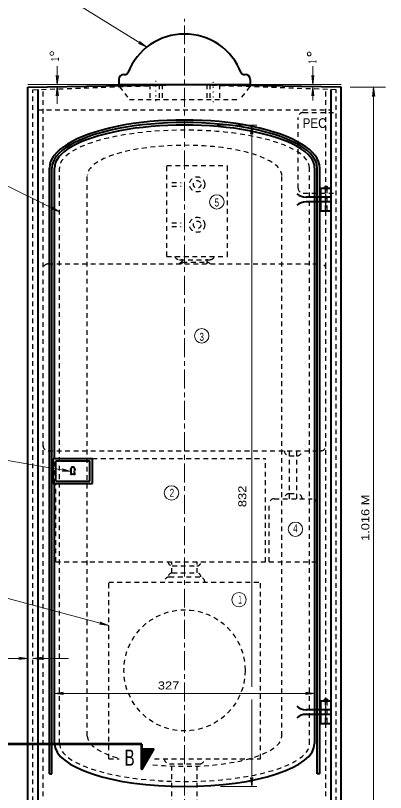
# Model space of a CAD drawing. Extents: x 312583 to 312853, y 144419 to 144586.
# Drawn here: x 312636.2 to 312671.3, y 144456.3 to 144530 of the extents above; entities that cross this region are included whole.
import ezdxf
from ezdxf.enums import TextEntityAlignment as Align

# ---------------------------------------------------------------- set-up
doc = ezdxf.new("R2010")
doc.units = 0
doc.header["$LTSCALE"] = 0.3
for name, pattern in [('DOTTED', [1.5, 0.3, -1.2]), ('LONG_DASH_SHORT_DASH', [9.9, 6, -1.2, 1.5, -1.2]), ('SHORT_DASHED', [2.7, 1.5, -1.2])]:
    doc.linetypes.add(name, pattern=pattern)
doc.layers.add('1', color=7, linetype='Continuous', lineweight=40)
doc.layers.add('2', color=7, linetype='Continuous', lineweight=13)

msp = doc.modelspace()

# ---------------------------------------------------------------- linework, layer by layer
at = {"layer": '1', "linetype": 'LONG_DASH_SHORT_DASH', "lineweight": 13}
msp.add_line((312652.2386, 144444.1359), (312652.2386, 144529.7113), dxfattribs=at)
at = {"layer": '1'}
for p, q in [((312646.0133, 144523.9613), (312646.0133, 144523.4859)), ((312646.4886, 144524.4443), (312646.6573, 144524.4443)), ((312657.8276, 144524.4443), (312657.9886, 144524.4443)), ((312658.4716, 144523.9613), (312658.4716, 144523.4859)), ((312637.3883, 144523.2253), (312652.2386, 144523.4859)), ((312637.3883, 144448.2376), (312637.3883, 144523.2253)), ((312646.0133, 144523.4859), (312658.4716, 144523.4859)), ((312646.0133, 144523.4859), (312658.4716, 144523.4859)), ((312667.0966, 144523.2253), (312652.2386, 144523.4859)), ((312667.0966, 144448.2376), (312667.0966, 144523.2253)), ((312638.3466, 144453.0293), (312638.3466, 144523.0029)), ((312666.1383, 144453.0293), (312666.1383, 144523.0029)), ((312639.4276, 144458.0586), (312639.4276, 144515.5586)), ((312639.6653, 144458.0586), (312639.6653, 144515.5586)), ((312639.9029, 144488.0046), (312639.9029, 144515.5586)), ((312664.5819, 144460.9336), (312664.5819, 144515.5586)), ((312664.8196, 144458.0586), (312664.8196, 144515.5586)), ((312665.0573, 144458.0586), (312665.0573, 144515.5586)), ((312665.1799, 144513.6419), (312666.1383, 144513.6419)), ((312665.1799, 144511.4876), (312665.1799, 144513.6419)), ((312666.1076, 144512.7833), (312663.7693, 144512.7833)), ((312666.1076, 144512.3463), (312663.7693, 144512.3463)), ((312665.1799, 144511.4876), (312666.1383, 144511.4876)), ((312639.7803, 144488.0046), (312643.4986, 144488.0046)), ((312639.7803, 144485.6126), (312639.7803, 144488.0046)), ((312643.4986, 144485.6126), (312643.4986, 144488.0046)), ((312640.0256, 144487.7669), (312643.2609, 144487.7669)), ((312640.0256, 144485.8503), (312640.0256, 144487.7669)), ((312643.2609, 144485.8503), (312643.2609, 144487.7669)), ((312639.7803, 144485.6126), (312643.4986, 144485.6126)), ((312639.9029, 144460.9336), (312639.9029, 144485.6126)), ((312640.0256, 144485.8503), (312643.2609, 144485.8503)), ((312665.1799, 144465.0046), (312666.1383, 144465.0046)), ((312665.1799, 144462.8503), (312665.1799, 144465.0046)), ((312666.1076, 144464.1459), (312663.7693, 144464.1459)), ((312666.1076, 144463.7089), (312663.7693, 144463.7089)), ((312665.1799, 144462.8503), (312666.1383, 144462.8503)), ((312639.4276, 144458.0586), (312639.6653, 144458.0586)), ((312665.0573, 144458.0586), (312664.8196, 144458.0586))]:
    msp.add_line(p, q, dxfattribs=at)
at = {"layer": '1', "linetype": 'SHORT_DASHED', "lineweight": 25}
for p, q in [((312637.8636, 144522.9876), (312652.2386, 144523.4859)), ((312646.0746, 144523.2713), (312647.0176, 144522.0446)), ((312648.9343, 144523.4859), (312648.9343, 144522.0446)), ((312649.8466, 144523.4859), (312649.8466, 144522.0446)), ((312650.1303, 144523.4859), (312650.1303, 144522.0446)), ((312666.6136, 144522.9876), (312652.2386, 144523.4859)), ((312654.3546, 144523.4859), (312654.3546, 144522.0446)), ((312654.6383, 144523.4859), (312654.6383, 144522.0446)), ((312655.5506, 144523.4859), (312655.5506, 144522.0446)), ((312658.4103, 144523.2713), (312657.4673, 144522.0446)), ((312637.8636, 144446.5586), (312637.8636, 144522.9876)), ((312638.8219, 144453.5046), (312638.8219, 144523.0183)), ((312665.6553, 144453.5046), (312665.6553, 144523.0183)), ((312666.6136, 144446.5586), (312666.6136, 144522.9876)), ((312647.0176, 144522.0446), (312657.4673, 144522.0446)), ((312638.3466, 144521.0709), (312666.1383, 144521.0709)), ((312663.0256, 144513.6419), (312663.0256, 144520.3503)), ((312663.5009, 144520.8333), (312666.6136, 144520.8333)), ((312650.5673, 144515.7963), (312656.3173, 144515.7963)), ((312650.5673, 144507.1713), (312650.5673, 144515.7963)), ((312656.3173, 144507.1713), (312656.3173, 144515.7963)), ((312640.3859, 144460.9336), (312640.3859, 144515.5586)), ((312664.0989, 144460.9336), (312664.0989, 144515.5586)), ((312643.0156, 144461.6543), (312643.0156, 144514.8379)), ((312661.4693, 144461.6543), (312661.4693, 144514.8379)), ((312651.0349, 144514.1863), (312651.9166, 144514.1863)), ((312651.0349, 144513.8259), (312651.9166, 144513.8259)), ((312665.5709, 144513.6343), (312665.5709, 144511.4799)), ((312665.7473, 144513.6343), (312665.7473, 144511.4799)), ((312663.5009, 144513.1666), (312666.6136, 144513.1666)), ((312651.0349, 144510.3529), (312651.9166, 144510.3529)), ((312651.0349, 144509.9926), (312651.9166, 144509.9926)), ((312650.5673, 144507.1713), (312656.3173, 144507.1713)), ((312652.0009, 144506.4583), (312652.0009, 144507.1713)), ((312654.4006, 144506.4583), (312654.4006, 144507.1713)), ((312639.3049, 144506.4583), (312665.1799, 144506.4583)), ((312651.7633, 144506.8569), (312654.6383, 144506.8569)), ((312652.0393, 144506.6193), (312654.3623, 144506.6193)), ((312639.3049, 144488.7253), (312665.1799, 144488.7253)), ((312662.1823, 144484.1713), (312662.1823, 144488.7253)), ((312662.9029, 144484.1713), (312662.9029, 144488.7253)), ((312639.9029, 144485.6126), (312639.9029, 144488.0046)), ((312643.4986, 144488.0046), (312659.9053, 144488.0046)), ((312662.1823, 144488.2499), (312662.9029, 144488.2499)), ((312640.0256, 144478.1836), (312640.0256, 144485.6126)), ((312660.7486, 144484.1713), (312664.3443, 144484.1713)), ((312662.1823, 144484.6543), (312662.9029, 144484.6543)), ((312660.2656, 144478.1836), (312660.2656, 144483.6959)), ((312651.0426, 144477.1333), (312651.0426, 144478.1836)), ((312651.0809, 144477.7926), (312653.4039, 144477.7926)), ((312653.4423, 144477.1333), (312653.4423, 144478.1836)), ((312660.2656, 144478.1836), (312664.8196, 144478.1836)), ((312650.8049, 144476.7499), (312653.6799, 144476.7499)), ((312651.0809, 144477.1333), (312653.4039, 144477.1333)), ((312645.0549, 144476.2669), (312659.4299, 144476.2669)), ((312645.0549, 144459.4999), (312645.0549, 144476.2669)), ((312659.4299, 144459.4999), (312659.4299, 144476.2669)), ((312665.5709, 144464.9969), (312665.5709, 144462.8503)), ((312665.7473, 144464.9969), (312665.7473, 144462.8503)), ((312645.0549, 144459.4999), (312646.0516, 144459.4999)), ((312649.3943, 144459.4999), (312659.4299, 144459.4999)), ((312650.8049, 144459.0169), (312653.6799, 144459.0169)), ((312651.0426, 144447.0416), (312651.0426, 144459.0169)), ((312653.4423, 144447.0416), (312653.4423, 144459.0169))]:
    msp.add_line(p, q, dxfattribs=at)
at = {"layer": '1', "linetype": 'DOTTED', "lineweight": 13}
for p, q in [((312649.5323, 144523.8386), (312649.5323, 144521.6613)), ((312654.9526, 144523.7389), (312654.9526, 144521.6613))]:
    msp.add_line(p, q, dxfattribs=at)
at = {"layer": '1', "lineweight": 53}
for p, q in [((312648.1983, 144460.8876), (312631.6076, 144460.8876)), ((312648.1983, 144460.4123), (312648.1983, 144460.8876))]:
    msp.add_line(p, q, dxfattribs=at)
at = {"layer": '1', "lineweight": 35}
for p, q in [((312648.1983, 144460.3969), (312649.0186, 144459.9216)), ((312648.1983, 144460.3663), (312649.0109, 144459.8986)), ((312648.1983, 144460.3356), (312648.9956, 144459.8756)), ((312648.1983, 144460.3126), (312648.9879, 144459.8603)), ((312648.1983, 144460.2819), (312648.9726, 144459.8373)), ((312648.1983, 144460.2053), (312648.9419, 144459.7759)), ((312648.1983, 144460.1746), (312648.9266, 144459.7529)), ((312648.1983, 144460.1439), (312648.9113, 144459.7376)), ((312648.1983, 144460.1209), (312648.9036, 144459.7146)), ((312648.1983, 144460.0903), (312648.8883, 144459.6916)), ((312648.1983, 144460.0596), (312648.8729, 144459.6686)), ((312648.1983, 144460.0366), (312648.8653, 144459.6533)), ((312648.1983, 144459.9753), (312648.8423, 144459.6073)), ((312648.1983, 144459.9523), (312648.8269, 144459.5919)), ((312648.1983, 144459.9293), (312648.8193, 144459.5689)), ((312648.1983, 144459.8986), (312648.8039, 144459.5459)), ((312648.1983, 144459.8679), (312648.7963, 144459.5306)), ((312648.1983, 144459.8373), (312648.7809, 144459.5076)), ((312648.1983, 144459.8143), (312648.7733, 144459.4846)), ((312648.1983, 144459.7836), (312648.7579, 144459.4693)), ((312648.2059, 144460.2589), (312648.9649, 144459.8143)), ((312648.2059, 144460.2283), (312648.9496, 144459.7989)), ((312648.2059, 144460.0059), (312648.8499, 144459.6303)), ((312648.2059, 144459.7606), (312648.7503, 144459.4386)), ((312648.2213, 144460.4123), (312649.0339, 144459.9369)), ((312648.2749, 144460.4123), (312649.0416, 144459.9676)), ((312648.3133, 144460.4123), (312649.0569, 144459.9829)), ((312648.3669, 144460.4123), (312649.0646, 144460.0059)), ((312648.4129, 144460.4123), (312649.0799, 144460.0289)), ((312648.4589, 144460.4123), (312649.0953, 144460.0443)), ((312648.5049, 144460.4123), (312649.1029, 144460.0673)), ((312648.5586, 144460.4123), (312649.1183, 144460.0903)), ((312648.6046, 144460.4123), (312649.1336, 144460.1056)), ((312648.6506, 144460.4123), (312649.1413, 144460.1286)), ((312648.7043, 144460.4123), (312649.1566, 144460.1439)), ((312648.7503, 144460.4123), (312649.1643, 144460.1669)), ((312648.7963, 144460.4123), (312649.1796, 144460.1899)), ((312648.8499, 144460.4123), (312649.1873, 144460.2053)), ((312648.8959, 144460.4123), (312649.2026, 144460.2359)), ((312648.9419, 144460.4123), (312649.2103, 144460.2513)), ((312648.9879, 144460.4123), (312649.2256, 144460.2743)), ((312649.0416, 144460.4123), (312649.2333, 144460.2973)), ((312649.0799, 144460.4123), (312649.2486, 144460.3126)), ((312649.1336, 144460.4123), (312649.2563, 144460.3356)), ((312649.1796, 144460.4123), (312649.2716, 144460.3586)), ((312649.2333, 144460.4123), (312649.2869, 144460.3739)), ((312649.2793, 144460.4123), (312649.2946, 144460.3969)), ((312648.1983, 144459.7299), (312648.7349, 144459.4233)), ((312648.1983, 144459.7069), (312648.7196, 144459.4003)), ((312648.1983, 144459.6763), (312648.7119, 144459.3773)), ((312648.1983, 144459.6456), (312648.6966, 144459.3619)), ((312648.1983, 144459.6226), (312648.6889, 144459.3389)), ((312648.1983, 144459.5919), (312648.6736, 144459.3159)), ((312648.1983, 144459.5613), (312648.6659, 144459.3006)), ((312648.1983, 144459.5383), (312648.6506, 144459.2776)), ((312648.1983, 144459.5076), (312648.6429, 144459.2546)), ((312648.1983, 144459.4769), (312648.6276, 144459.2393)), ((312648.1983, 144459.4539), (312648.6199, 144459.2163)), ((312648.1983, 144459.4309), (312648.6046, 144459.1933)), ((312648.1983, 144459.4003), (312648.5969, 144459.1703)), ((312648.1983, 144459.3696), (312648.5816, 144459.1549)), ((312648.1983, 144459.3389), (312648.5663, 144459.1319)), ((312648.1983, 144459.3159), (312648.5586, 144459.1089)), ((312648.1983, 144459.2853), (312648.5433, 144459.0936)), ((312648.1983, 144459.2623), (312648.5279, 144459.0706)), ((312648.1983, 144459.2316), (312648.5203, 144459.0476)), ((312648.1983, 144459.2086), (312648.5049, 144459.0323)), ((312648.1983, 144459.1779), (312648.4973, 144459.0093)), ((312648.1983, 144459.1473), (312648.4819, 144458.9863)), ((312648.1983, 144459.1243), (312648.4743, 144458.9709)), ((312648.1983, 144459.0936), (312648.4589, 144458.9403)), ((312648.1983, 144459.0706), (312648.4513, 144458.9249)), ((312648.1983, 144459.0399), (312648.4359, 144458.9019)), ((312648.1983, 144459.0093), (312648.4283, 144458.8789)), ((312648.1983, 144458.9863), (312648.4129, 144458.8636)), ((312648.1983, 144458.9556), (312648.4053, 144458.8406)), ((312648.1983, 144458.9326), (312648.3899, 144458.8176)), ((312648.1983, 144458.9019), (312648.3746, 144458.8023)), ((312648.1983, 144458.8713), (312648.3669, 144458.7793)), ((312648.1983, 144458.8406), (312648.3516, 144458.7563)), ((312648.1983, 144458.8176), (312648.3363, 144458.7409)), ((312648.1983, 144458.7869), (312648.3286, 144458.7179)), ((312648.1983, 144458.7639), (312648.3133, 144458.6949)), ((312648.1983, 144458.7409), (312648.3056, 144458.6719)), ((312648.1983, 144458.7103), (312648.2903, 144458.6566)), ((312648.1983, 144458.6796), (312648.2826, 144458.6336)), ((312648.1983, 144458.6489), (312648.2673, 144458.6106)), ((312648.1983, 144458.6259), (312648.2596, 144458.5953)), ((312648.1983, 144458.5953), (312648.2443, 144458.5723)), ((312648.1983, 144458.5723), (312648.2366, 144458.5493)), ((312648.1983, 144458.5416), (312648.2213, 144458.5339)), ((312648.1983, 144458.5109), (312648.2136, 144458.5109))]:
    msp.add_line(p, q, dxfattribs=at)
at = {"layer": '1', "linetype": 'SHORT_DASHED', "lineweight": 25}
msp.add_lwpolyline([(312640.0256, 144478.1836), (312659.9053, 144478.1836), (312659.9053, 144488.0046)], dxfattribs=at)
at = {"layer": '1', "lineweight": 53}
msp.add_lwpolyline([(312648.1983, 144460.4123), (312649.3099, 144460.4123), (312648.1983, 144458.4956)], close=True, dxfattribs=at)
at = {"layer": '1', "linetype": 'SHORT_DASHED', "lineweight": 25}
for centre, radius in [((312653.4384, 144514.0023), 0.7188), ((312653.4384, 144514.0023), 0.3594), ((312653.4384, 144510.1689), 0.7188), ((312653.4384, 144510.1689), 0.3594), ((312652.2405, 144467.8815), 5.75)]:
    msp.add_circle(centre, radius, dxfattribs=at)
at = {"layer": '1'}
for centre, radius, start, end in [((312652.2405, 144522.5257), 5.75, 21.1002, 158.90079), ((312646.4905, 144523.9632), 0.4792, 90, 180), ((312646.6525, 144524.6819), 0.2396, 270, 338.8998), ((312657.8285, 144524.6819), 0.2396, 201.1002, 270), ((312657.9905, 144523.9632), 0.4792, 0, 90), ((312665.6585, 144513.5971), 0.1954, 17.35766, 165.56497), ((312665.6568, 144513.6088), 0.1465, 17.35766, 165.56497), ((312665.6569, 144513.6205), 0.0977, 17.35766, 165.56497), ((312665.6528, 144513.638), 0.0244, 17.35766, 165.56497), ((312663.8309, 144514.3033), 1.5233, 231.73709, 267.53516), ((312663.8309, 144510.8244), 1.5233, 92.46484, 128.26291), ((312641.6413, 144486.9926), 0.184, 0.60951, 179.40319), ((312640.5502, 144486.7229), 0.9469, 343.7422, 16.66705), ((312641.6394, 144486.0304), 0.4638, 67.14337, 112.85662), ((312642.7286, 144486.7229), 0.9469, 163.33295, 196.2578), ((312665.6585, 144464.9616), 0.1954, 17.35766, 165.56497), ((312665.6568, 144464.9733), 0.1465, 17.35766, 165.56497), ((312665.6569, 144464.985), 0.0977, 17.35766, 165.56497), ((312665.6528, 144465.0026), 0.0244, 17.35766, 165.56497), ((312663.8309, 144465.6678), 1.5233, 231.73709, 267.53516), ((312663.8309, 144462.1889), 1.5233, 92.46484, 128.26291)]:
    msp.add_arc(centre, radius, start, end, dxfattribs=at)
at = {"layer": '1', "linetype": 'SHORT_DASHED', "lineweight": 25}
for centre, radius, start, end in [((312663.5009, 144520.3503), 0.4792, 90, 180), ((312663.5009, 144513.6419), 0.4792, 180, 270), ((312651.7613, 144507.3361), 0.4792, 199.98311, 270), ((312654.6363, 144507.3361), 0.4792, 270, 340.11484), ((312639.303, 144505.9753), 0.4792, 90, 180), ((312652.0356, 144506.229), 0.3881, 90.0198, 144.53298), ((312654.3643, 144506.229), 0.3881, 35.49, 90.0198), ((312665.178, 144505.9753), 0.4792, 0, 90), ((312639.303, 144489.2044), 0.4792, 180, 270), ((312662.1842, 144488.7272), 0.4792, 180, 270), ((312662.9029, 144488.7272), 0.4792, 270, 0), ((312665.178, 144489.2044), 0.4792, 270, 0), ((312660.7467, 144483.694), 0.4792, 90, 180), ((312662.1842, 144484.1732), 0.4792, 90, 180), ((312662.9029, 144484.1732), 0.4792, 0, 90), ((312664.3423, 144483.694), 0.4792, 0, 90), ((312651.0772, 144478.1828), 0.3881, 180, 270), ((312653.406, 144478.1828), 0.3881, 270, 0), ((312650.803, 144476.2669), 0.4792, 90, 180), ((312651.0772, 144476.7469), 0.3881, 90, 180), ((312653.406, 144476.7469), 0.3881, 0, 90), ((312653.678, 144476.2669), 0.4792, 0, 90), ((312650.803, 144459.4961), 0.4792, 180, 270), ((312653.678, 144459.4961), 0.4792, 270, 0)]:
    msp.add_arc(centre, radius, start, end, dxfattribs=at)
at = {"layer": '1'}
for centre, major_axis, ratio, start_param, end_param in [((312652.2415, 144515.5586), (12.8177, 0), 0.35514, 6.2831853, 9.424778), ((312652.2415, 144515.5586), (12.5781, 0), 0.342857, 6.2831853, 9.424778), ((312652.2415, 144515.5586), (12.3385, 0), 0.330097, 6.2831853, 9.424778), ((312652.2415, 144460.9336), (12.3385, 0), 0.330097, 3.1415927, 6.2831853)]:
    msp.add_ellipse(centre, major_axis=major_axis, ratio=ratio, start_param=start_param, end_param=end_param, dxfattribs=at)
at = {"layer": '1', "linetype": 'SHORT_DASHED', "lineweight": 25}
for centre, major_axis, ratio, start_param, end_param in [((312652.2415, 144515.5586), (11.8594, 0), 0.30303, 6.2831853, 9.424778), ((312652.2415, 144514.8398), (-9.224, 0), 0.311688, 3.1415927, 6.2831853), ((312652.2415, 144461.6523), (-9.224, 0), 0.311688, 6.2831853, 7.1291245), ((312652.2415, 144461.6523), (-9.224, 0), 0.311688, 1.2393571, 3.1415927), ((312652.2415, 144460.9336), (11.8594, 0), 0.30303, 3.1415927, 6.2831853)]:
    msp.add_ellipse(centre, major_axis=major_axis, ratio=ratio, start_param=start_param, end_param=end_param, dxfattribs=at)
at = {"layer": '2'}
for p, q in [((312647.8686, 144527.3883), (312648.1523, 144527.3346)), ((312648.6583, 144527.0203), (312647.8686, 144527.3883)), ((312647.9759, 144527.5723), (312648.1523, 144527.3346)), ((312648.6583, 144527.0203), (312647.9759, 144527.5723)), ((312640.1713, 144523.4859), (312640.1713, 144525.2339)), ((312664.4056, 144523.4859), (312664.4056, 144525.2339)), ((312640.0639, 144524.3523), (312640.1713, 144524.0763)), ((312640.1713, 144523.4859), (312640.0639, 144524.3523)), ((312640.2786, 144524.3523), (312640.1713, 144524.0763)), ((312640.1713, 144523.4859), (312640.2786, 144524.3523)), ((312664.2983, 144524.3523), (312664.4056, 144524.0763)), ((312664.4056, 144523.4859), (312664.2983, 144524.3523)), ((312664.5129, 144524.3523), (312664.4056, 144524.0763)), ((312664.4056, 144523.4859), (312664.5129, 144524.3523)), ((312652.2386, 144523.4859), (312637.3883, 144523.4859)), ((312640.1713, 144523.2713), (312640.0639, 144522.4049)), ((312640.1713, 144521.6536), (312640.1713, 144523.2713)), ((312640.1713, 144523.2713), (312640.2786, 144522.4049)), ((312652.2386, 144523.4859), (312667.0966, 144523.4859)), ((312664.4056, 144523.2713), (312664.2983, 144522.4049)), ((312664.4056, 144521.9679), (312664.4056, 144523.2713)), ((312664.4056, 144523.2713), (312664.5129, 144522.4049)), ((312667.9399, 144523.2253), (312671.2944, 144523.2253)), ((312670.1754, 144523.2253), (312670.0681, 144522.3589)), ((312670.1754, 144446.5586), (312670.1754, 144523.2253)), ((312670.1754, 144523.2253), (312670.2827, 144522.3589)), ((312640.0639, 144522.4049), (312640.1713, 144522.6809)), ((312640.2786, 144522.4049), (312640.1713, 144522.6809)), ((312664.2983, 144522.4049), (312664.4056, 144522.6809)), ((312664.5129, 144522.4049), (312664.4056, 144522.6809)), ((312670.0681, 144522.3589), (312670.1754, 144522.6349)), ((312670.2827, 144522.3589), (312670.1754, 144522.6349)), ((312655.3436, 144519.6296), (312659.1079, 144519.6296)), ((312658.6096, 144519.6296), (312658.5023, 144518.7633)), ((312658.6096, 144466.3309), (312658.6096, 144519.6296)), ((312658.6096, 144519.6296), (312658.7169, 144518.7633)), ((312658.5023, 144518.7633), (312658.6096, 144519.0393)), ((312658.7169, 144518.7633), (312658.6096, 144519.0393)), ((312640.3859, 144511.4033), (312634.5516, 144514.2706)), ((312639.5579, 144511.6946), (312639.8569, 144511.6639)), ((312640.3859, 144511.4033), (312639.5579, 144511.6946)), ((312639.6499, 144511.8863), (312639.8569, 144511.6639)), ((312640.3859, 144511.4033), (312639.6499, 144511.8863)), ((312641.4976, 144486.7626), (312633.9306, 144488.0583)), ((312640.6236, 144486.8009), (312640.9149, 144486.8623)), ((312641.4976, 144486.7626), (312640.6236, 144486.8009)), ((312640.6619, 144487.0156), (312640.9149, 144486.8623)), ((312641.4976, 144486.7626), (312640.6619, 144487.0156)), ((312645.0549, 144472.1423), (312634.2373, 144475.0556)), ((312644.1886, 144472.2649), (312644.4876, 144472.2956)), ((312644.2423, 144472.4719), (312644.4876, 144472.2956)), ((312645.0549, 144472.1423), (312644.2423, 144472.4719)), ((312645.0549, 144472.1423), (312644.1886, 144472.2649)), ((312635.2799, 144469.0219), (312637.3883, 144469.0219)), ((312636.5219, 144469.1293), (312636.7979, 144469.0219)), ((312637.3883, 144469.0219), (312636.5219, 144469.1293)), ((312636.5219, 144468.9146), (312636.7979, 144469.0219)), ((312637.3883, 144469.0219), (312636.5219, 144468.9146)), ((312637.8636, 144469.0219), (312638.7299, 144469.1293)), ((312637.8636, 144469.0219), (312641.2216, 144469.0219)), ((312637.8636, 144469.0219), (312638.7299, 144468.9146)), ((312638.7299, 144469.1293), (312638.4539, 144469.0219)), ((312638.7299, 144468.9146), (312638.4539, 144469.0219)), ((312639.9029, 144465.6946), (312640.7693, 144465.8019)), ((312639.9029, 144465.6946), (312664.5819, 144465.6946)), ((312639.9029, 144465.6946), (312640.7693, 144465.5873)), ((312640.7693, 144465.8019), (312640.4933, 144465.6946)), ((312640.7693, 144465.5873), (312640.4933, 144465.6946)), ((312663.7156, 144465.8019), (312663.9916, 144465.6946)), ((312664.5819, 144465.6946), (312663.7156, 144465.8019)), ((312663.7156, 144465.5873), (312663.9916, 144465.6946)), ((312664.5819, 144465.6946), (312663.7156, 144465.5873)), ((312658.6096, 144456.8626), (312658.6096, 144465.1196)), ((312658.5023, 144457.7289), (312658.6096, 144457.4529)), ((312658.6096, 144456.8626), (312658.5023, 144457.7289)), ((312658.7169, 144457.7289), (312658.6096, 144457.4529)), ((312658.6096, 144456.8626), (312658.7169, 144457.7289)), ((312655.6579, 144456.8626), (312659.1079, 144456.8626))]:
    msp.add_line(p, q, dxfattribs=at)
msp.add_lwpolyline([(312648.6583, 144527.0203), (312639.5426, 144532.6783), (312638.0246, 144532.6783)], dxfattribs=at)
for centre, radius in [((312639.65, 144526.4259), 0.1797), ((312664.0663, 144526.3838), 0.1797), ((312655.3034, 144512.3443), 0.6818), ((312653.8697, 144499.633), 0.6818), ((312651.0024, 144484.7214), 0.6818), ((312662.7592, 144481.2809), 0.6818), ((312657.4079, 144474.5898), 0.6818)]:
    msp.add_circle(centre, radius, dxfattribs=at)

# ---------------------------------------------------------------- texts
at = {"layer": '1', "width": 0.7}
msp.add_text('B', height=1.533, dxfattribs=at).set_placement((312647.0291, 144458.8329), align=Align.CENTER)
at = {"layer": '2'}
for s, width, p in [('1', 0.5, (312640.3337, 144525.7074)), ('1', 0.5, (312664.7481, 144525.4668)), ('832 ', 1.2, (312658.0947, 144483.3773)), ('1.016 M', 1.2, (312669.7667, 144480.1607))]:
    msp.add_text(s, height=0.76, rotation=90, dxfattribs=dict(at, width=width)).set_placement(p)
for s, height, width, p in [('PEC', 0.92, 0.9, (312663.4319, 144519.3613)), ('5', 0.76, 0.75, (312655.0928, 144511.9055)), ('3', 0.76, 0.75, (312653.6591, 144499.1586)), ('2', 0.76, 0.75, (312650.8273, 144484.3533)), ('4', 0.76, 0.75, (312662.5448, 144480.9819)), ('1', 0.76, 0.5, (312657.3282, 144474.218)), ('327 ', 0.76, 1.2, (312649.7101, 144466.0684))]:
    msp.add_text(s, height=height, dxfattribs=dict(at, width=width)).set_placement(p)

doc.saveas('drawing.dxf')
